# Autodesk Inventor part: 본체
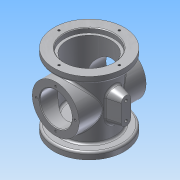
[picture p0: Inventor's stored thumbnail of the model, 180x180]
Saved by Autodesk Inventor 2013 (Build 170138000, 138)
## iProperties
Created: 2018-02
Part Number: 본체
Material: 알루미늄 6061
Document SubType Name: Modeling
Designer: Administrator
Density: 2.71 g/cm^3
Mass: 771.812 g
Surface Area: 820.857 cm^2
Volume: 284.802 cm^3
Author: Administrator
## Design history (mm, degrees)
sketch "스케치1"
  geometry: C1 r 38 at (0, 0); 1 further point
  constraints: 1 centre point, 1 coincident
  dimensions: "d0" = 38 radius of C1
extrude "돌출1" new body sketch "스케치1" stored distance "d1" = 108; taper "d2" = 0 deg
sketch "스케치2"
  geometry: C1 r 38 at (0, 0) reference; C2 r 52.5 at (0, 0)
  constraints: 1 centre point, 1 coincident
  dimensions: "d4" = 105 diameter of C2
extrude "돌출2" join sketch "스케치2" distance "d5" = 10; taper "d6" = 0 deg
sketch "스케치3"
  geometry: C1 r 38 at (0, 0) reference; C2 r 52.5 at (0, 0)
  constraints: 1 centre point, 1 coincident
  dimensions: "d7" = 105 diameter of C2
extrude "돌출3" join sketch "스케치3" distance "d8" = 10; taper "d9" = 0 deg
sketch "스케치4"
  geometry: C1 r 52.5 at (0, 0) reference; C2 r 34 at (0, 0)
  constraints: 1 centre point, 1 coincident
  dimensions: "d10" = 68 diameter of C2
extrude "돌출4" cut sketch "스케치4" distance "d11" = 16; taper "d12" = 0 deg
sketch "스케치5"
  geometry: C1 r 52.5 at (0, 0) reference; C2 r 37 at (0, 0)
  constraints: 1 centre point, 1 coincident
  dimensions: "d13" = 74 diameter of C2
extrude "돌출5" cut sketch "스케치5" distance "d14" = 7; taper "d15" = 0 deg
sketch "스케치6"
  geometry: C1 r 37 at (0, 0) reference; C2 r 33 at (0, 0)
  constraints: 1 centre point, 1 coincident
  dimensions: "d16" = 66 diameter of C2
extrude "돌출6" cut sketch "스케치6" distance "d17" = 79; taper "d18" = 0 deg
node "작업 평면1"
sketch "스케치7"
  geometry: C1 r 35 at (0, 0); 1 further point
  constraints: 1 centre point, 1 coincident
  dimensions: "d20" = 70 diameter of C1
extrude "돌출7" join sketch "스케치7" stored distance "d21" = 79; taper "d22" = 0 deg
sketch "스케치8" dims "d23" = 58
  geometry: C1 r 35 at (0, 0) reference; 5 further points
  constraints: 2 vertical alignment, 1 coincident, 7 other
  dimensions: "d26" = 360 deg dimension on C1.centre point (0, 29) (derived)
hole "구멍1" sketch "스케치8" at (0, 29), (-29, 0), (0, -29), (29, 0) diameter "d28" = 3.242; stored, may be unused: countersink angle "d32" = 90 deg, drill point angle "d34" = 118 deg; dims "d29" = 4, "d30" = 4, "d31" = 2, "d33" = 6
sketch "스케치9"
  geometry: C1 r 35 at (0, 0) reference; C2 r 24 at (0, 0)
  constraints: 1 centre point, 1 coincident
  dimensions: "d35" = 48 diameter of C2
extrude "돌출8" cut sketch "스케치9" stored distance "d36" = 79; taper "d37" = 0 deg
sketch "스케치10" dims "d38" = 90
  geometry: C1 r 37 at (0, 0) reference; C2 r 52.5 at (0, 0) reference; 5 further points
  constraints: 2 vertical alignment, 1 coincident, 7 other
  dimensions: "d41" = 360 deg dimension on C1.centre point (0, 45) (derived)
hole "구멍2" sketch "스케치10" at (0, 45), (-45, 0), (0, -45), (45, 0) diameter "d43" = 3.242; stored, may be unused: countersink angle "d47" = 90 deg, drill point angle "d49" = 118 deg; dims "d44" = 4, "d45" = 4, "d46" = 2, "d48" = 6
sketch "스케치11"
  geometry: C1 r 34 at (0, 0) reference; 1 further point
  constraints: 1 coincident
hole "구멍3" sketch "스케치11" at (0, 0) diameter "d50" = 10; stored, may be unused: countersink angle "d54" = 90 deg, drill point angle "d56" = 118 deg; dims "d51" = 4, "d52" = 4, "d53" = 2, "d55" = 6
node "작업 평면2"
sketch "스케치12"
  geometry: L1 (-13, 7)-(13, 7); L2 (-13, -7)-(13, -7); A1 r 7 centre (13, 0) between (13, 7) and (13, -7); A2 r 7 centre (-13, 0) between (-13, 7) and (-13, -7); 1 further point
  constraints: 4 end point, 4 point on circle, 3 tangent, 2 centre point, 2 horizontal alignment, 1 horizontal
  dimensions: "d58" = 14 diameter of A1; "d59" = 14 diameter of A2; "d60" = 13 distance of A1.centre point (0, 0); "d61" = 13 distance of point (0, 0) A2.centre
extrude "돌출9" join sketch "스케치12" stored distance "d62" = 79; taper "d63" = 15 deg
sketch "스케치13"
  geometry: A1 r 7 centre (0, 13) between (7, 13) and (-7, 13) reference; A2 r 7 centre (0, -13) between (-7, -13) and (7, -13) reference; 3 further points
  constraints: 2 coincident
hole "구멍4" sketch "스케치13" at (0, 13), (0, -13) diameter "d64" = 4.134; stored, may be unused: countersink angle "d68" = 90 deg, drill point angle "d70" = 118 deg; dims "d65" = 6, "d66" = 4, "d67" = 2, "d69" = 8
fillet "모깎기1" dims "d72" = 3
fillet "모깎기2" dims "d73" = 3
fillet "모깎기3" dims "d74" = 3
fillet "모깎기4" dims "d75" = 3
fillet "모깎기5" dims "d76" = 3
fillet "모깎기6" dims "d77" = 3
chamfer "모따기1" distance "d78" = 1; stored, may be unused: second distance "d79" = 2, angle "d80" = 45 deg
node "솔리드1"
mirror "대칭1"
other parameters: "d57" = 55
